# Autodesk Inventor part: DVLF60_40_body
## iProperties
Created: 2010-03
Part Number: DVLF60_40_body
Document SubType Name: Modeling
Designer: TB
Mass: 688.638 g
Surface Area: 1349.83 cm^2
Volume: 688.638 cm^3
Density: 1 g/cm^3
Author: TB
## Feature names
1. Kropp [Revolution]
2. Chamfer
3. Extrusion2
4. Hole1
5. Revolution2
6. Hole2
7. Fillet1
8. Extrusion3
9. Hole3
